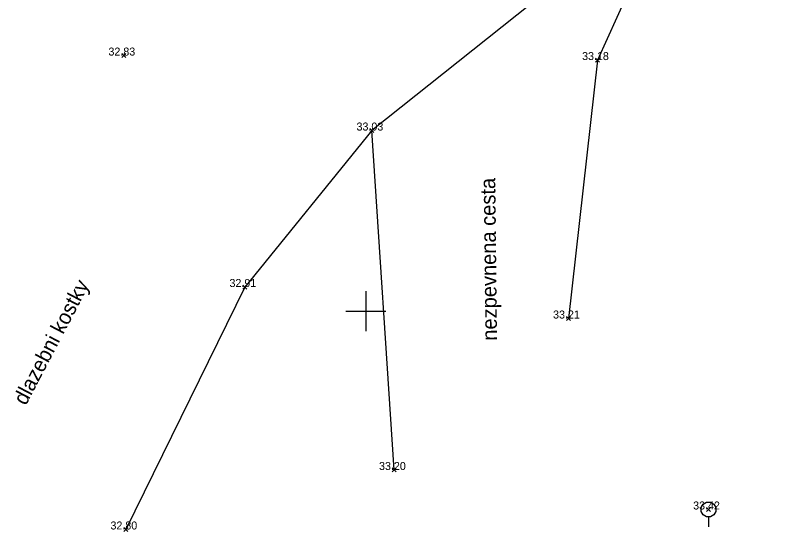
# Model space of a CAD drawing. Extents: x -772865 to -772533, y -1034366 to -1034132.
# Drawn here: x -772807 to -772791.49, y -1034304.41 to -1034294.09 of the extents above; entities that cross this region are included whole.
import ezdxf

# ---------------------------------------------------------------- set-up
doc = ezdxf.new("R2010")
doc.units = 0
for name, color, linetype in [('body', 7, 'Continuous'), ('kanalizace', 7, 'Continuous'), ('mistni_popis', 7, 'Continuous'), ('oddeleni_ploch', 7, 'Continuous'), ('souradnicova_sit', 7, 'Continuous'), ('vyskove_koty', 7, 'Continuous')]:
    doc.layers.add(name, color=color, linetype=linetype)

msp = doc.modelspace()

# ---------------------------------------------------------------- linework, layer by layer
at = {"layer": 'body'}
for p, q in [((-772804.8, -1034294.93), (-772804.88, -1034294.85)), ((-772804.88, -1034294.93), (-772804.8, -1034294.85)), ((-772795.33, -1034295.02), (-772795.41, -1034294.94)), ((-772795.41, -1034295.02), (-772795.33, -1034294.94)), ((-772799.84, -1034296.43), (-772799.92, -1034296.35)), ((-772799.92, -1034296.43), (-772799.84, -1034296.35)), ((-772802.38, -1034299.56), (-772802.46, -1034299.48)), ((-772802.46, -1034299.56), (-772802.38, -1034299.48)), ((-772795.91, -1034300.19), (-772795.99, -1034300.11)), ((-772795.99, -1034300.19), (-772795.91, -1034300.11)), ((-772799.39, -1034303.22), (-772799.47, -1034303.14)), ((-772799.47, -1034303.22), (-772799.39, -1034303.14)), ((-772793.11, -1034304.01), (-772793.19, -1034303.93)), ((-772793.19, -1034304.01), (-772793.11, -1034303.93)), ((-772804.76, -1034304.41), (-772804.84, -1034304.33)), ((-772804.84, -1034304.41), (-772804.76, -1034304.33))]:
    msp.add_line(p, q, dxfattribs=at)
at = {"layer": 'kanalizace'}
msp.add_line((-772793.158, -1034303.97), (-772793.138, -1034303.97), dxfattribs=at)
msp.add_lwpolyline([(-772793.15, -1034304.114), (-772793.188, -1034304.114), (-772793.256, -1034304.076), (-772793.294, -1034304.008), (-772793.294, -1034303.93), (-772793.256, -1034303.862), (-772793.188, -1034303.824), (-772793.11, -1034303.824), (-772793.042, -1034303.862), (-772793.004, -1034303.93), (-772793.004, -1034304.008), (-772793.042, -1034304.076), (-772793.11, -1034304.114), (-772793.148, -1034304.114), (-772793.148, -1034304.32)], dxfattribs=at)
at = {"layer": 'oddeleni_ploch'}
msp.add_line((-772799.43, -1034303.18), (-772799.88, -1034296.39), dxfattribs=at)
for points in [[(-772689.63, -1034259.88), (-772704.53, -1034266.45), (-772719.18, -1034273.09), (-772731.59, -1034278.63), (-772738.33, -1034281.57), (-772742.46, -1034279.19), (-772747.03, -1034275.55), (-772755.44, -1034275.22), (-772763.58, -1034277.24), (-772782.03, -1034284.79), (-772793.82, -1034291.56), (-772799.88, -1034296.39), (-772802.42, -1034299.52), (-772804.8, -1034304.37)], [(-772793.82, -1034291.56), (-772795.37, -1034294.98), (-772795.95, -1034300.15)]]:
    msp.add_lwpolyline(points, dxfattribs=at)
at = {"layer": 'souradnicova_sit'}
for p, q in [((-772800, -1034299.6), (-772800, -1034300.4)), ((-772800.4, -1034300), (-772799.6, -1034300))]:
    msp.add_line(p, q, dxfattribs=at)

# ---------------------------------------------------------------- texts
at = {"layer": 'mistni_popis'}
for s, rotation, p in [('nezpevnena cesta', 90.6419, (-772797.375, -1034300.592)), ('dlazebni kostky', 62.2805, (-772806.798, -1034301.903))]:
    msp.add_text(s, height=0.3, rotation=rotation, dxfattribs=at).set_placement(p)
at = {"layer": 'vyskove_koty'}
for s, p in [('32.83', (-772805.145, -1034294.89)), ('33.18', (-772795.675, -1034294.98)), ('33.03', (-772800.185, -1034296.39)), ('32.91', (-772802.725, -1034299.52)), ('33.21', (-772796.255, -1034300.15)), ('33.20', (-772799.735, -1034303.18)), ('33.42', (-772793.455, -1034303.97)), ('32.80', (-772805.105, -1034304.37))]:
    msp.add_text(s, height=0.16, dxfattribs=at).set_placement(p)

doc.saveas('drawing.dxf')
